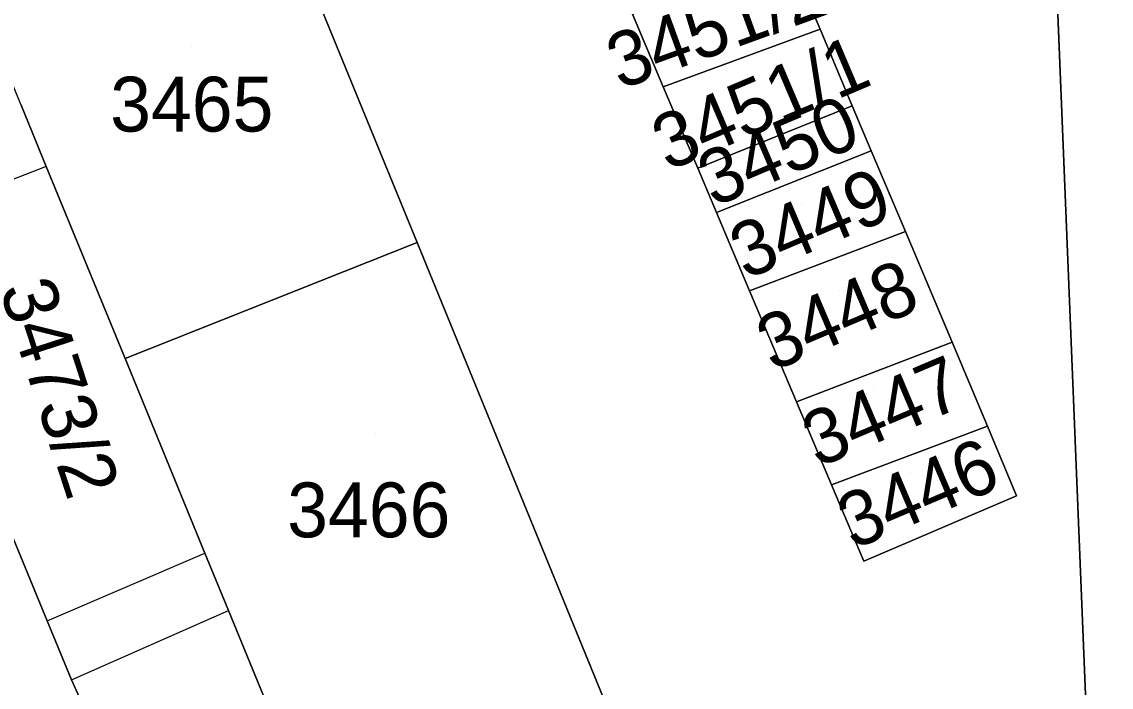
# Model space of a CAD drawing. Extents: x -264070 to -262271, y -1238894 to -1238141.
# Drawn here: x -262788.62 to -262748.9, y -1238450.62 to -1238426.34 of the extents above; entities that cross this region are included whole.
import ezdxf

# ---------------------------------------------------------------- set-up
doc = ezdxf.new("R2010")
doc.units = 0
for name, color, linetype in [('body_kn', 7, 'Continuous'), ('kladpar_druhypozemkov', 7, 'Continuous'), ('kladpar_hranice', 7, 'Continuous'), ('kladpar_parcelnecisla', 7, 'Continuous'), ('kladpar_plochy', 7, 'Continuous'), ('zappar_hrandruhpozemk', 7, 'Continuous')]:
    doc.layers.add(name, color=color, linetype=linetype)

msp = doc.modelspace()

# ---------------------------------------------------------------- linework, layer by layer
at = {"layer": 'body_kn'}
for p, q in [((-262759.51, -1238426.62), (-262759.51, -1238426.62)), ((-262759.51, -1238426.62), (-262759.51, -1238426.62)), ((-262765.23, -1238428.72), (-262765.23, -1238428.72)), ((-262758.34, -1238429.41), (-262758.34, -1238429.41)), ((-262758.34, -1238429.41), (-262758.34, -1238429.41)), ((-262757.65, -1238431.05), (-262757.65, -1238431.05)), ((-262757.65, -1238431.05), (-262757.65, -1238431.05)), ((-262787.73, -1238431.62), (-262787.73, -1238431.62)), ((-262787.73, -1238431.62), (-262787.73, -1238431.62)), ((-262763.97, -1238431.68), (-262763.97, -1238431.68)), ((-262763.29, -1238433.3), (-262763.29, -1238433.3)), ((-262756.4, -1238434), (-262756.4, -1238434)), ((-262756.4, -1238434), (-262756.4, -1238434)), ((-262774.2, -1238434.4), (-262774.2, -1238434.4)), ((-262774.2, -1238434.4), (-262774.2, -1238434.4)), ((-262762.08, -1238436.16), (-262762.08, -1238436.16)), ((-262754.7, -1238438.03), (-262754.7, -1238438.03)), ((-262754.7, -1238438.03), (-262754.7, -1238438.03)), ((-262784.85, -1238438.63), (-262784.85, -1238438.63)), ((-262760.37, -1238440.21), (-262760.37, -1238440.21)), ((-262753.41, -1238441.1), (-262753.41, -1238441.1)), ((-262753.41, -1238441.1), (-262753.41, -1238441.1)), ((-262759.1, -1238443.23), (-262759.1, -1238443.23)), ((-262752.35, -1238443.64), (-262752.35, -1238443.64)), ((-262781.94, -1238445.73), (-262781.94, -1238445.73)), ((-262757.92, -1238446.02), (-262757.92, -1238446.02)), ((-262781.08, -1238447.82), (-262781.08, -1238447.82)), ((-262787.7, -1238448.2), (-262787.7, -1238448.2)), ((-262787.7, -1238448.2), (-262787.7, -1238448.2)), ((-262786.81, -1238450.35), (-262786.81, -1238450.35)), ((-262786.81, -1238450.35), (-262786.81, -1238450.35))]:
    msp.add_line(p, q, dxfattribs=at)
at = {"layer": 'kladpar_druhypozemkov'}
for p, q in [((-262782.43, -1238427.25), (-262782.43, -1238427.25)), ((-262762.06, -1238428.39), (-262762.06, -1238428.39)), ((-262760.71, -1238430.58), (-262760.71, -1238430.58)), ((-262760.2, -1238433), (-262760.2, -1238433)), ((-262758.79, -1238436.13), (-262758.79, -1238436.13)), ((-262757.57, -1238439.76), (-262757.57, -1238439.76)), ((-262775.73, -1238441.35), (-262775.73, -1238441.35)), ((-262756.2, -1238442.77), (-262756.2, -1238442.77))]:
    msp.add_line(p, q, dxfattribs=at)
at = {"layer": 'kladpar_hranice'}
for points in [[(-262749.29, -1238464.34), (-262752.45, -1238386.59), (-262752.59, -1238380.59), (-262753.09, -1238372.1), (-262752.66, -1238372.09), (-262752.74, -1238366.16), (-262753.23, -1238366.16), (-262753.23, -1238365.87), (-262753.24, -1238363.91), (-262747.97, -1238363.88), (-262747.99, -1238366.99), (-262748.01, -1238369.71), (-262748.03, -1238372.89), (-262748.05, -1238376.02), (-262745.22, -1238375.9), (-262742.02, -1238375.77), (-262729.38, -1238375.23)], [(-262752.45, -1238386.59), (-262749.29, -1238464.34)], [(-262709.67, -1238479.66), (-262729.53, -1238476.4), (-262732.07, -1238474.26), (-262739.16, -1238472.01), (-262771.66, -1238470.79), (-262772.39, -1238469.03), (-262761.87, -1238464.6), (-262767.41, -1238451.02), (-262774.2, -1238434.4), (-262779.73, -1238420.89), (-262785.23, -1238407.4), (-262792.2, -1238390.33)], [(-262779.73, -1238420.89), (-262774.2, -1238434.4), (-262784.85, -1238438.63), (-262787.73, -1238431.62), (-262788.64, -1238429.39), (-262790.31, -1238425.34), (-262779.73, -1238420.89)], [(-262760.63, -1238423.96), (-262759.51, -1238426.62), (-262765.23, -1238428.72), (-262766.35, -1238426.07), (-262760.63, -1238423.96)], [(-262763.97, -1238431.68), (-262763.29, -1238433.3), (-262762.08, -1238436.16), (-262760.37, -1238440.21), (-262759.1, -1238443.23), (-262757.92, -1238446.02), (-262752.35, -1238443.64), (-262753.41, -1238441.1), (-262754.7, -1238438.03), (-262756.4, -1238434), (-262757.65, -1238431.05), (-262758.34, -1238429.41), (-262759.51, -1238426.62), (-262760.63, -1238423.96)], [(-262766.35, -1238426.07), (-262765.23, -1238428.72), (-262763.97, -1238431.68)], [(-262759.51, -1238426.62), (-262758.34, -1238429.41), (-262763.97, -1238431.68), (-262765.23, -1238428.72), (-262759.51, -1238426.62)], [(-262788.64, -1238429.39), (-262787.73, -1238431.62)], [(-262758.34, -1238429.41), (-262757.65, -1238431.05), (-262763.29, -1238433.3), (-262763.97, -1238431.68), (-262758.34, -1238429.41)], [(-262757.65, -1238431.05), (-262756.4, -1238434), (-262762.08, -1238436.16), (-262763.29, -1238433.3), (-262757.65, -1238431.05)], [(-262787.73, -1238431.62), (-262784.85, -1238438.63), (-262781.94, -1238445.73), (-262781.08, -1238447.82), (-262778.06, -1238455.2), (-262774.99, -1238462.69), (-262774.1, -1238464.84), (-262772.39, -1238469.03), (-262771.66, -1238470.79), (-262773.42, -1238470.67), (-262776.21, -1238470.23), (-262779.9, -1238466.91), (-262780.7, -1238464.86), (-262784.06, -1238456.43), (-262786.81, -1238450.35), (-262787.7, -1238448.2), (-262793.58, -1238433.92)], [(-262793.58, -1238433.92), (-262787.7, -1238448.2), (-262786.81, -1238450.35), (-262784.06, -1238456.43), (-262780.7, -1238464.86), (-262786.55, -1238466.5), (-262791, -1238467.76)], [(-262756.4, -1238434), (-262754.7, -1238438.03), (-262760.37, -1238440.21), (-262762.08, -1238436.16), (-262756.4, -1238434)], [(-262774.2, -1238434.4), (-262767.41, -1238451.02), (-262778.06, -1238455.2), (-262781.08, -1238447.82), (-262781.94, -1238445.73), (-262784.85, -1238438.63), (-262774.2, -1238434.4)], [(-262754.7, -1238438.03), (-262753.41, -1238441.1), (-262759.1, -1238443.23), (-262760.37, -1238440.21), (-262754.7, -1238438.03)], [(-262753.41, -1238441.1), (-262752.35, -1238443.64), (-262757.92, -1238446.02), (-262759.1, -1238443.23), (-262753.41, -1238441.1)]]:
    msp.add_lwpolyline(points, dxfattribs=at)
at = {"layer": 'kladpar_plochy'}
for p, q in [((-262752.45, -1238386.59), (-262749.29, -1238464.34)), ((-262774.2, -1238434.4), (-262779.73, -1238420.89)), ((-262759.51, -1238426.62), (-262760.63, -1238423.96)), ((-262766.35, -1238426.07), (-262765.23, -1238428.72)), ((-262758.34, -1238429.41), (-262759.51, -1238426.62)), ((-262765.23, -1238428.72), (-262763.97, -1238431.68)), ((-262757.65, -1238431.05), (-262758.34, -1238429.41)), ((-262756.4, -1238434), (-262757.65, -1238431.05)), ((-262763.97, -1238431.68), (-262763.29, -1238433.3)), ((-262763.29, -1238433.3), (-262762.08, -1238436.16)), ((-262754.7, -1238438.03), (-262756.4, -1238434)), ((-262767.41, -1238451.02), (-262774.2, -1238434.4)), ((-262762.08, -1238436.16), (-262760.37, -1238440.21)), ((-262753.41, -1238441.1), (-262754.7, -1238438.03)), ((-262760.37, -1238440.21), (-262759.1, -1238443.23)), ((-262752.35, -1238443.64), (-262753.41, -1238441.1)), ((-262759.1, -1238443.23), (-262757.92, -1238446.02)), ((-262757.92, -1238446.02), (-262752.35, -1238443.64))]:
    msp.add_line(p, q, dxfattribs=at)
for points in [[(-262749.29, -1238464.34), (-262752.45, -1238386.59), (-262752.59, -1238380.59), (-262753.09, -1238372.1), (-262752.66, -1238372.09), (-262752.74, -1238366.16), (-262753.23, -1238366.16), (-262753.23, -1238365.87), (-262753.24, -1238363.91), (-262747.97, -1238363.88), (-262747.99, -1238366.99), (-262748.01, -1238369.71), (-262748.03, -1238372.89), (-262748.05, -1238376.02), (-262745.22, -1238375.9), (-262742.02, -1238375.77), (-262729.38, -1238375.23), (-262727.62, -1238375.13), (-262720.72, -1238374.82)], [(-262788.64, -1238429.39), (-262787.73, -1238431.62), (-262784.85, -1238438.63), (-262781.94, -1238445.73), (-262781.08, -1238447.82), (-262778.06, -1238455.2), (-262774.99, -1238462.69), (-262774.1, -1238464.84), (-262772.39, -1238469.03), (-262771.66, -1238470.79), (-262773.42, -1238470.67), (-262776.21, -1238470.23), (-262779.9, -1238466.91), (-262780.7, -1238464.86), (-262784.06, -1238456.43), (-262786.81, -1238450.35), (-262787.7, -1238448.2), (-262793.58, -1238433.92)], [(-262793.58, -1238433.92), (-262787.7, -1238448.2), (-262786.81, -1238450.35), (-262784.06, -1238456.43), (-262780.7, -1238464.86), (-262786.55, -1238466.5), (-262791, -1238467.76)]]:
    msp.add_lwpolyline(points, dxfattribs=at)
for points in [[(-262779.73, -1238420.89), (-262774.2, -1238434.4), (-262784.85, -1238438.63), (-262787.73, -1238431.62), (-262788.64, -1238429.39), (-262790.31, -1238425.34)], [(-262760.63, -1238423.96), (-262759.51, -1238426.62), (-262765.23, -1238428.72), (-262766.35, -1238426.07)], [(-262759.51, -1238426.62), (-262758.34, -1238429.41), (-262763.97, -1238431.68), (-262765.23, -1238428.72)], [(-262758.34, -1238429.41), (-262757.65, -1238431.05), (-262763.29, -1238433.3), (-262763.97, -1238431.68)], [(-262757.65, -1238431.05), (-262756.4, -1238434), (-262762.08, -1238436.16), (-262763.29, -1238433.3)], [(-262756.4, -1238434), (-262754.7, -1238438.03), (-262760.37, -1238440.21), (-262762.08, -1238436.16)], [(-262774.2, -1238434.4), (-262767.41, -1238451.02), (-262778.06, -1238455.2), (-262781.08, -1238447.82), (-262781.94, -1238445.73), (-262784.85, -1238438.63)], [(-262754.7, -1238438.03), (-262753.41, -1238441.1), (-262759.1, -1238443.23), (-262760.37, -1238440.21)], [(-262753.41, -1238441.1), (-262752.35, -1238443.64), (-262757.92, -1238446.02), (-262759.1, -1238443.23)]]:
    msp.add_lwpolyline(points, close=True, dxfattribs=at)
at = {"layer": 'zappar_hrandruhpozemk'}
for p, q in [((-262787.73, -1238431.62), (-262793.58, -1238433.92)), ((-262787.7, -1238448.2), (-262781.94, -1238445.73)), ((-262786.81, -1238450.35), (-262781.08, -1238447.82))]:
    msp.add_line(p, q, dxfattribs=at)

# ---------------------------------------------------------------- texts
at = {"layer": 'kladpar_parcelnecisla'}
for s, rotation, p in [('3451/2', 20, (-262766.81, -1238428.832)), ('3451/1', 23, (-262765.065, -1238431.807)), ('3450', 23, (-262763.396, -1238433.12)), ('3449', 23, (-262762.226, -1238435.766)), ('3448', 23, (-262761.248, -1238439.115)), ('3473/2', 288, (-262789.445, -1238436.094)), ('3447', 23, (-262759.593, -1238442.627)), ('3446', 23, (-262758.306, -1238445.616))]:
    msp.add_text(s, height=2, rotation=rotation, dxfattribs=at).set_placement(p)
for s, p in [('3465', (-262785.397, -1238430.35)), ('3466', (-262778.942, -1238445.15))]:
    msp.add_text(s, height=2, dxfattribs=at).set_placement(p)

doc.saveas('drawing.dxf')
